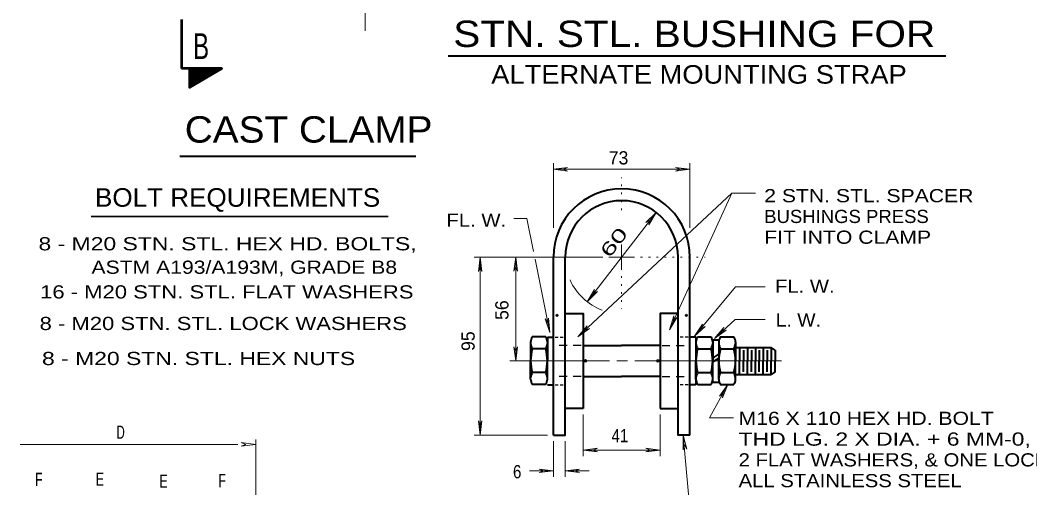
# Model space of a CAD drawing. Extents: x 312583 to 312854, y 144419 to 144597.
# Drawn here: x 312665.2 to 312723.4, y 144516.8 to 144543.7 of the extents above; entities that cross this region are included whole.
import ezdxf
from ezdxf.enums import TextEntityAlignment as Align

# ---------------------------------------------------------------- set-up
doc = ezdxf.new("R2010")
doc.units = 0
doc.header["$LTSCALE"] = 0.3
doc.header["$PDMODE"] = 32
doc.header["$PDSIZE"] = 0.15
doc.linetypes.add('DOTTED', pattern=[1.5, 0.3, -1.2])
doc.linetypes.add('SHORT_DASHED', pattern=[2.7, 1.5, -1.2])
doc.layers.add('1', color=7, linetype='Continuous', lineweight=13)

msp = doc.modelspace()

# ---------------------------------------------------------------- linework, layer by layer
at = {"layer": '1'}
for p, q in [((312685.0876, 144545.2113), (312685.0876, 144543.1183)), ((312695.9432, 144531.7582), (312695.9432, 144535.4842)), ((312703.8169, 144531.7582), (312703.8169, 144535.4842)), ((312695.9432, 144535.1392), (312696.7635, 144535.2389)), ((312695.9432, 144535.1392), (312703.8169, 144535.1392)), ((312695.9432, 144535.1392), (312696.7635, 144535.0396)), ((312696.7635, 144535.2389), (312696.5029, 144535.1392)), ((312696.7635, 144535.0396), (312696.5029, 144535.1392)), ((312702.9889, 144535.2389), (312703.2495, 144535.1392)), ((312703.8169, 144535.1392), (312702.9889, 144535.2389)), ((312702.9889, 144535.0396), (312703.2495, 144535.1392)), ((312703.8169, 144535.1392), (312702.9889, 144535.0396)), ((312697.3539, 144525.4716), (312706.2319, 144533.7592)), ((312702.6285, 144525.8932), (312706.2319, 144533.7592)), ((312706.2319, 144533.7592), (312707.5965, 144533.7592)), ((312697.8982, 144527.4956), (312701.8619, 144532.6552)), ((312701.8619, 144532.6552), (312701.2792, 144532.0649)), ((312701.8619, 144532.6552), (312701.4402, 144531.9422)), ((312693.6586, 144532.3102), (312694.4099, 144532.3102)), ((312694.4099, 144532.3102), (312694.7932, 144530.4012)), ((312701.2792, 144532.0649), (312701.5169, 144532.2106)), ((312701.4402, 144531.9422), (312701.5169, 144532.2106)), ((312699.8762, 144530.0792), (312699.8762, 144530.8076)), ((312698.7875, 144530.0792), (312691.3739, 144530.0792)), ((312691.7189, 144530.0792), (312691.6192, 144529.2512)), ((312691.6192, 144529.2512), (312691.7189, 144529.5119)), ((312691.7189, 144530.0792), (312691.7189, 144519.8059)), ((312691.7189, 144530.0792), (312691.8185, 144529.2512)), ((312691.8185, 144529.2512), (312691.7189, 144529.5119)), ((312693.7735, 144530.0792), (312693.6662, 144529.2589)), ((312693.6662, 144529.2589), (312693.7735, 144529.5196)), ((312693.7735, 144524.0916), (312693.7735, 144530.0792)), ((312693.7735, 144530.0792), (312693.8732, 144529.2589)), ((312693.8732, 144529.2589), (312693.7735, 144529.5196)), ((312694.8852, 144529.9489), (312695.7285, 144525.7322)), ((312699.8762, 144530.0792), (312699.1479, 144530.0792)), ((312699.8762, 144530.0792), (312699.8762, 144529.3432)), ((312699.8762, 144530.0792), (312700.6122, 144530.0792)), ((312706.4465, 144528.3619), (312704.0852, 144525.5099)), ((312706.4465, 144528.3619), (312708.1562, 144528.3619)), ((312697.8982, 144527.4956), (312698.3199, 144528.2162)), ((312697.8982, 144527.4956), (312698.4809, 144528.0859)), ((312698.3199, 144528.2162), (312698.2432, 144527.9402)), ((312698.4809, 144528.0859), (312698.2432, 144527.9402)), ((312702.6285, 144525.8932), (312702.8815, 144526.6829)), ((312702.8815, 144526.6829), (312702.8585, 144526.4069)), ((312695.4679, 144526.5219), (312695.6212, 144526.2842)), ((312695.7285, 144525.7322), (312695.4679, 144526.5219)), ((312695.6672, 144526.5602), (312695.6212, 144526.2842)), ((312695.7285, 144525.7322), (312695.6672, 144526.5602)), ((312697.3539, 144525.4716), (312697.8829, 144526.1079)), ((312697.8829, 144526.1079), (312697.7602, 144525.8549)), ((312702.6285, 144525.8932), (312703.0579, 144526.5986)), ((312703.0579, 144526.5986), (312702.8585, 144526.4069)), ((312704.0852, 144525.5099), (312704.5375, 144526.2076)), ((312704.0852, 144525.5099), (312704.6909, 144526.0772)), ((312704.5375, 144526.2076), (312704.4455, 144525.9392)), ((312704.6909, 144526.0772), (312704.4455, 144525.9392)), ((312706.4159, 144526.4836), (312705.2275, 144525.3796)), ((312706.4159, 144526.4836), (312708.1485, 144526.4836)), ((312697.3539, 144525.4716), (312698.0285, 144525.9622)), ((312698.0285, 144525.9622), (312697.7602, 144525.8549)), ((312705.2275, 144525.3796), (312705.7642, 144526.0159)), ((312705.2275, 144525.3796), (312705.9022, 144525.8626)), ((312705.7642, 144526.0159), (312705.6415, 144525.7629)), ((312705.9022, 144525.8626), (312705.6415, 144525.7629)), ((312693.6662, 144524.9119), (312693.7735, 144524.6512)), ((312693.7735, 144524.0916), (312693.6662, 144524.9119)), ((312693.8732, 144524.9119), (312693.7735, 144524.6512)), ((312693.7735, 144524.0916), (312693.8732, 144524.9119)), ((312699.1862, 144524.0916), (312693.4285, 144524.0916)), ((312700.2212, 144524.0916), (312699.5925, 144524.0916)), ((312700.6352, 144524.0916), (312709.0992, 144524.0916)), ((312706.0019, 144522.7269), (312704.9515, 144520.8026)), ((312706.0019, 144522.7269), (312705.5189, 144522.0522)), ((312706.0019, 144522.7269), (312705.7029, 144521.9602)), ((312705.5189, 144522.0522), (312705.7335, 144522.2362)), ((312705.7029, 144521.9602), (312705.7335, 144522.2362)), ((312697.6529, 144518.6099), (312697.6529, 144521.0096)), ((312702.1072, 144518.6099), (312702.1072, 144521.0096)), ((312706.3239, 144520.8026), (312704.9515, 144520.8026)), ((312691.6192, 144520.6339), (312691.7189, 144520.3732)), ((312691.7189, 144519.8059), (312691.6192, 144520.6339)), ((312691.8185, 144520.6339), (312691.7189, 144520.3732)), ((312691.7189, 144519.8059), (312691.8185, 144520.6339)), ((312695.5982, 144519.8059), (312691.3739, 144519.8059)), ((312703.4335, 144519.8059), (312703.4265, 144518.9762)), ((312703.4335, 144519.8059), (312703.6281, 144518.9962)), ((312665.1937, 144519.2818), (312677.7363, 144519.2818)), ((312677.9433, 144519.3891), (312678.2117, 144519.2818)), ((312678.7867, 144519.2818), (312677.9433, 144519.3891)), ((312677.9433, 144519.1821), (312678.2117, 144519.2818)), ((312678.7867, 144519.2818), (312677.9433, 144519.1821)), ((312678.7867, 144513.9841), (312678.7867, 144519.5578)), ((312695.9432, 144519.4686), (312695.9432, 144517.4062)), ((312696.6255, 144519.4686), (312696.6255, 144517.4062)), ((312697.6529, 144518.9549), (312698.4809, 144519.0546)), ((312698.4809, 144519.0546), (312698.2125, 144518.9549)), ((312701.2792, 144519.0546), (312701.5475, 144518.9549)), ((312702.1072, 144518.9549), (312701.2792, 144519.0546)), ((312703.4265, 144518.9762), (312703.4963, 144519.2502)), ((312703.6281, 144518.9962), (312703.4963, 144519.2502)), ((312697.6529, 144518.9549), (312702.1072, 144518.9549)), ((312697.6529, 144518.9549), (312698.4809, 144518.8552)), ((312698.4809, 144518.8552), (312698.2125, 144518.9549)), ((312701.2792, 144518.8552), (312701.5475, 144518.9549)), ((312702.1072, 144518.9549), (312701.2792, 144518.8552)), ((312695.9432, 144517.7512), (312694.5709, 144517.7512)), ((312695.1152, 144517.8509), (312695.3835, 144517.7512)), ((312695.9432, 144517.7512), (312695.1152, 144517.8509)), ((312695.1152, 144517.6516), (312695.3835, 144517.7512)), ((312695.9432, 144517.7512), (312695.1152, 144517.6516)), ((312696.6255, 144517.7512), (312697.4535, 144517.8509)), ((312697.9979, 144517.7512), (312696.6255, 144517.7512)), ((312696.6255, 144517.7512), (312697.4535, 144517.6516)), ((312697.4535, 144517.8509), (312697.1852, 144517.7512)), ((312697.4535, 144517.6516), (312697.1852, 144517.7512))]:
    msp.add_line(p, q, dxfattribs=at)
at = {"layer": '1', "lineweight": 53}
for p in [(312674.4922, 144543.7776), (312674.9522, 144540.9409)]:
    msp.add_line(p, (312674.4922, 144540.9409), dxfattribs=at)
at = {"layer": '1', "lineweight": 40}
for p, q in [((312689.8769, 144541.6789), (312718.5793, 144541.6789)), ((312674.4041, 144535.8982), (312688.0124, 144535.8982)), ((312695.9432, 144519.8059), (312695.9432, 144530.0792)), ((312703.8169, 144519.8059), (312703.8169, 144530.0792)), ((312695.5062, 144525.4716), (312694.7242, 144525.4716)), ((312695.5982, 144525.4562), (312695.9432, 144525.4562)), ((312695.5982, 144525.4562), (312695.5982, 144524.0916)), ((312704.1619, 144525.4562), (312703.8169, 144525.4562)), ((312704.1619, 144525.4562), (312704.1619, 144522.7192)), ((312704.2462, 144525.4716), (312705.0359, 144525.4716)), ((312705.5649, 144525.4716), (312706.3469, 144525.4716)), ((312694.6245, 144525.1726), (312694.6245, 144524.0839)), ((312695.5982, 144525.1726), (312695.5982, 144524.0916)), ((312697.6529, 144524.9886), (312699.8762, 144524.9886)), ((312702.1072, 144524.9886), (312699.8762, 144524.9886)), ((312704.1619, 144525.1726), (312704.1619, 144524.0916)), ((312705.1279, 144525.3106), (312705.4729, 144525.3106)), ((312705.1279, 144525.3106), (312705.1279, 144525.1726)), ((312705.1279, 144525.1726), (312705.1279, 144524.0839)), ((312705.4729, 144525.3106), (312705.4729, 144525.1726)), ((312705.4729, 144525.1726), (312705.4729, 144524.0839)), ((312706.4465, 144525.1649), (312706.4465, 144524.0839)), ((312706.6765, 144524.8736), (312706.6765, 144524.0839)), ((312707.1289, 144524.8736), (312707.1289, 144524.0839)), ((312707.5889, 144524.8736), (312707.5889, 144524.0839)), ((312708.0412, 144524.8736), (312708.0412, 144524.0839)), ((312708.7312, 144524.7126), (312708.5012, 144524.8736)), ((312695.5062, 144524.7892), (312694.7242, 144524.7892)), ((312704.2539, 144524.7892), (312705.0359, 144524.7892)), ((312705.1279, 144524.2602), (312705.4729, 144524.4826)), ((312705.5649, 144524.7816), (312706.3469, 144524.7816)), ((312706.9065, 144524.7126), (312706.9065, 144524.0839)), ((312707.3589, 144524.7126), (312707.3589, 144524.0839)), ((312707.8112, 144524.7126), (312707.8112, 144524.0839)), ((312708.2712, 144524.7126), (312708.2712, 144524.0839)), ((312708.7312, 144524.7126), (312708.7312, 144524.0839)), ((312694.6245, 144523.0336), (312694.6245, 144524.0916)), ((312695.5982, 144523.0336), (312695.5982, 144524.0916)), ((312704.1619, 144523.0336), (312704.1619, 144524.0916)), ((312705.1279, 144524.0302), (312705.4729, 144524.2526)), ((312705.1279, 144523.0336), (312705.1279, 144524.0916)), ((312705.4729, 144523.0259), (312705.4729, 144524.0839)), ((312706.4465, 144523.0336), (312706.4465, 144524.0916)), ((312706.6765, 144523.3019), (312706.6765, 144524.0916)), ((312706.9065, 144523.4629), (312706.9065, 144524.0916)), ((312707.1289, 144523.3019), (312707.1289, 144524.0916)), ((312707.3589, 144523.4629), (312707.3589, 144524.0916)), ((312707.5889, 144523.3019), (312707.5889, 144524.0916)), ((312707.8112, 144523.4629), (312707.8112, 144524.0916)), ((312708.0412, 144523.3019), (312708.0412, 144524.0916)), ((312708.2712, 144523.4629), (312708.2712, 144524.0916)), ((312708.5012, 144523.3019), (312708.5012, 144524.0916)), ((312708.7312, 144523.4629), (312708.7312, 144524.0916)), ((312695.5062, 144523.4246), (312694.7242, 144523.4246)), ((312697.6529, 144523.1869), (312699.8762, 144523.1869)), ((312702.1072, 144523.1869), (312699.8762, 144523.1869)), ((312704.2462, 144523.4246), (312705.0359, 144523.4246)), ((312705.5649, 144523.4246), (312706.3469, 144523.4246)), ((312706.4465, 144523.3019), (312708.5012, 144523.3019)), ((312708.7312, 144523.4629), (312708.5012, 144523.3019)), ((312695.5062, 144522.7346), (312694.7242, 144522.7346)), ((312695.5982, 144522.7192), (312695.9432, 144522.7192)), ((312704.1619, 144522.7192), (312703.8169, 144522.7192)), ((312704.2462, 144522.7346), (312705.0359, 144522.7346)), ((312705.1279, 144522.8726), (312705.1279, 144523.0336)), ((312705.1279, 144522.8726), (312705.4729, 144522.8726)), ((312705.4729, 144523.0259), (312705.4729, 144522.8726)), ((312705.5649, 144522.7269), (312706.3469, 144522.7269)), ((312697.6529, 144521.3469), (312696.6255, 144521.3469)), ((312702.1072, 144521.3469), (312703.1345, 144521.3469))]:
    msp.add_line(p, q, dxfattribs=at)
at = {"layer": '1', "lineweight": 35}
for p, q in [((312674.9522, 144540.9179), (312675.4122, 144540.1283)), ((312674.9522, 144540.8643), (312675.3816, 144540.1206)), ((312674.9522, 144540.8259), (312675.3739, 144540.1053)), ((312674.9522, 144540.7723), (312675.3509, 144540.0976)), ((312674.9522, 144540.7263), (312675.3279, 144540.0823)), ((312674.9522, 144540.6803), (312675.3126, 144540.0669)), ((312674.9522, 144540.6419), (312675.2896, 144540.0593)), ((312674.9522, 144540.5883), (312675.2666, 144540.0439)), ((312674.9676, 144540.9409), (312675.4276, 144540.1436)), ((312674.9982, 144540.9409), (312675.4506, 144540.1513)), ((312675.0289, 144540.9409), (312675.4736, 144540.1666)), ((312675.0519, 144540.9409), (312675.4889, 144540.1743)), ((312675.0826, 144540.9409), (312675.5119, 144540.1896)), ((312675.1056, 144540.9256), (312675.5349, 144540.1896)), ((312675.1286, 144540.9256), (312675.5502, 144540.2126)), ((312675.1516, 144540.9409), (312675.5732, 144540.2126)), ((312675.1822, 144540.9409), (312675.5962, 144540.2356)), ((312675.2129, 144540.9409), (312675.6116, 144540.2433)), ((312675.2359, 144540.9409), (312675.6269, 144540.2509)), ((312675.2666, 144540.9409), (312675.6499, 144540.2663)), ((312675.2972, 144540.9409), (312675.6729, 144540.2816)), ((312675.3202, 144540.9409), (312675.6882, 144540.2893)), ((312675.3509, 144540.9256), (312675.7112, 144540.3046)), ((312675.3739, 144540.9409), (312675.7342, 144540.3123)), ((312675.3969, 144540.9409), (312675.7496, 144540.3276)), ((312675.4199, 144540.9409), (312675.7726, 144540.3353)), ((312675.4506, 144540.9409), (312675.7956, 144540.3506)), ((312675.4812, 144540.9409), (312675.8109, 144540.3583)), ((312675.5119, 144540.9409), (312675.8339, 144540.3736)), ((312675.5349, 144540.9409), (312675.8569, 144540.3813)), ((312675.5656, 144540.9409), (312675.8646, 144540.3966)), ((312675.5886, 144540.9256), (312675.8952, 144540.4043)), ((312675.6192, 144540.9409), (312675.9106, 144540.4196)), ((312675.6422, 144540.9409), (312675.9336, 144540.4349)), ((312675.6652, 144540.9409), (312675.9566, 144540.4349)), ((312675.6959, 144540.9409), (312675.9719, 144540.4579)), ((312675.7189, 144540.9409), (312675.9949, 144540.4579)), ((312675.7496, 144540.9409), (312676.0179, 144540.4809)), ((312675.7802, 144540.9409), (312676.0332, 144540.4809)), ((312675.8032, 144540.9409), (312676.0562, 144540.4963)), ((312675.8339, 144540.9409), (312676.0792, 144540.5039)), ((312675.8646, 144540.9409), (312676.0869, 144540.5193)), ((312675.8876, 144540.9409), (312676.1099, 144540.5269)), ((312675.9029, 144540.9409), (312676.1329, 144540.5423)), ((312675.9336, 144540.9409), (312676.1559, 144540.5499)), ((312675.9642, 144540.9409), (312676.1712, 144540.5653)), ((312675.9949, 144540.9409), (312676.1942, 144540.5806)), ((312676.0179, 144540.9409), (312676.2172, 144540.5883)), ((312676.0486, 144540.9409), (312676.2326, 144540.6036)), ((312676.0716, 144540.9409), (312676.2556, 144540.6189)), ((312676.1022, 144540.9409), (312676.2786, 144540.6266)), ((312676.1176, 144540.9409), (312676.2939, 144540.6419)), ((312676.1482, 144540.9409), (312676.3169, 144540.6496)), ((312676.1789, 144540.9409), (312676.3322, 144540.6649)), ((312676.2019, 144540.9409), (312676.3552, 144540.6726)), ((312676.2326, 144540.9409), (312676.3782, 144540.6803)), ((312676.2556, 144540.9409), (312676.3936, 144540.6956)), ((312676.2862, 144540.9409), (312676.4166, 144540.7033)), ((312676.3169, 144540.9409), (312676.4396, 144540.7109)), ((312676.3322, 144540.9409), (312676.4549, 144540.7263)), ((312676.3629, 144540.9409), (312676.4779, 144540.7339)), ((312676.3859, 144540.9409), (312676.5009, 144540.7493)), ((312676.4166, 144540.9409), (312676.5162, 144540.7646)), ((312676.4472, 144540.9409), (312676.5392, 144540.7723)), ((312676.4779, 144540.9409), (312676.5622, 144540.7876)), ((312676.5009, 144540.9409), (312676.5776, 144540.8029)), ((312676.5316, 144540.9409), (312676.6006, 144540.8106)), ((312676.5546, 144540.9409), (312676.6236, 144540.8259)), ((312676.5776, 144540.9409), (312676.6389, 144540.8336)), ((312676.6006, 144540.9409), (312676.6542, 144540.8489)), ((312676.6312, 144540.9409), (312676.6772, 144540.8566)), ((312676.6619, 144540.9409), (312676.7002, 144540.8719)), ((312676.6849, 144540.9409), (312676.7156, 144540.8796)), ((312676.7156, 144540.9409), (312676.7386, 144540.8949)), ((312676.7386, 144540.9409), (312676.7616, 144540.9026)), ((312676.7692, 144540.9409), (312676.7769, 144540.9179)), ((312676.7999, 144540.9409), (312676.7999, 144540.9256)), ((312674.9522, 144540.5423), (312675.2512, 144540.0286)), ((312674.9522, 144540.4963), (312675.2282, 144540.0209)), ((312674.9522, 144540.4503), (312675.2129, 144540.0056)), ((312674.9522, 144540.4043), (312675.1899, 144539.9979)), ((312674.9522, 144540.3583), (312675.1669, 144539.9903)), ((312674.9522, 144540.3046), (312675.1516, 144539.9749)), ((312674.9522, 144540.2586), (312675.1286, 144539.9673)), ((312674.9522, 144540.2126), (312675.1056, 144539.9596)), ((312674.9522, 144540.1743), (312675.0902, 144539.9443)), ((312674.9522, 144540.1206), (312675.0672, 144539.9366)), ((312674.9522, 144540.0823), (312675.0519, 144539.9213)), ((312674.9522, 144540.0286), (312675.0289, 144539.9136)), ((312674.9522, 144539.9903), (312675.0059, 144539.8983)), ((312674.9522, 144539.9366), (312674.9906, 144539.8829)), ((312674.9522, 144539.8906), (312674.9676, 144539.8753)), ((312669.2792, 144532.4252), (312686.4218, 144532.4252))]:
    msp.add_line(p, q, dxfattribs=at)
at = {"layer": '1', "linetype": 'DOTTED'}
for p, q in [((312699.8762, 144532.7779), (312699.8762, 144534.6639)), ((312700.9725, 144530.0792), (312704.6909, 144530.0792)), ((312699.8762, 144528.9829), (312699.8762, 144527.1046))]:
    msp.add_line(p, q, dxfattribs=at)
at = {"layer": '1', "lineweight": 25}
for p, q in [((312696.0429, 144525.4562), (312696.2192, 144525.4562)), ((312696.3265, 144525.4562), (312696.5105, 144525.4562)), ((312703.4335, 144525.4562), (312703.2495, 144525.4562)), ((312703.7172, 144525.4562), (312703.5409, 144525.4562)), ((312696.0429, 144522.7192), (312696.2192, 144522.7192)), ((312696.3265, 144522.7192), (312696.5105, 144522.7192)), ((312703.4335, 144522.7192), (312703.2495, 144522.7192)), ((312703.7172, 144522.7192), (312703.5409, 144522.7192))]:
    msp.add_line(p, q, dxfattribs=at)
at = {"layer": '1', "linetype": 'SHORT_DASHED', "lineweight": 25}
for p, q in [((312697.5379, 144524.9886), (312696.0659, 144524.9886)), ((312702.2145, 144524.9886), (312703.6942, 144524.9886)), ((312697.5379, 144523.1869), (312696.0659, 144523.1869)), ((312702.2145, 144523.1869), (312703.6942, 144523.1869))]:
    msp.add_line(p, q, dxfattribs=at)
at = {"layer": '1', "lineweight": 53}
msp.add_lwpolyline([(312674.9522, 144540.9409), (312674.9522, 144539.8599), (312676.8152, 144540.9409)], close=True, dxfattribs=at)
at = {"layer": '1', "lineweight": 40}
for points in [[(312695.9432, 144519.8059), (312696.6255, 144519.8059), (312696.6255, 144530.0792)], [(312703.8169, 144519.8059), (312703.1345, 144519.8059), (312703.1345, 144530.0792)], [(312696.6255, 144526.8286), (312697.6529, 144526.8286), (312697.6529, 144521.3469)], [(312703.1345, 144526.8286), (312702.1072, 144526.8286), (312702.1072, 144521.3469)], [(312706.4465, 144524.8736), (312708.5012, 144524.8736), (312708.5012, 144524.0839)]]:
    msp.add_lwpolyline(points, dxfattribs=at)
at = {"layer": '1'}
msp.add_lwpolyline([(312703.4335, 144519.8059), (312703.8195, 144515.3367), (312702.4549, 144515.3367)], dxfattribs=at)
at = {"layer": '1', "lineweight": 40}
for centre, radius, start, end in [((312699.8795, 144530.0765), 3.9374, 90, 180), ((312699.8795, 144530.0765), 3.9374, 0, 90), ((312699.8795, 144530.0765), 3.2529, 90, 180), ((312699.8795, 144530.0765), 3.2529, 0, 90), ((312695.1905, 144525.1543), 0.5638, 145.8703, 178.33743), ((312695.0352, 144525.1543), 0.5638, 1.66257, 34.1297), ((312704.7238, 144525.1543), 0.5638, 145.8703, 178.33743), ((312704.5685, 144525.1543), 0.5638, 1.66257, 34.1297), ((312706.0381, 144525.1516), 0.5638, 145.8703, 178.33743), ((312705.8827, 144525.1516), 0.5638, 1.66257, 34.1297), ((312696.2058, 144525.4265), 1.6143, 191.77014, 203.36365), ((312694.0199, 144525.4265), 1.6143, 336.63635, 348.22986), ((312705.7391, 144525.4265), 1.6143, 191.77014, 203.36365), ((312703.5531, 144525.4265), 1.6143, 336.63635, 348.22986), ((312707.0534, 144525.4238), 1.6143, 191.77014, 203.36365), ((312704.8674, 144525.4238), 1.6143, 336.63635, 348.22986), ((312697.538, 144524.0322), 2.9134, 164.99798, 178.595), ((312692.6877, 144524.0322), 2.9134, 1.405, 15.00202), ((312707.0712, 144524.0322), 2.9134, 164.99798, 178.595), ((312702.221, 144524.0322), 2.9134, 1.405, 15.00202), ((312708.3855, 144524.0294), 2.9134, 164.99798, 178.595), ((312703.5353, 144524.0294), 2.9134, 1.405, 15.00202), ((312697.538, 144524.1751), 2.9134, 181.405, 195.00202), ((312692.6877, 144524.1751), 2.9134, 344.99798, 358.595), ((312707.0712, 144524.1751), 2.9134, 181.405, 195.00202), ((312702.221, 144524.1751), 2.9134, 344.99798, 358.595), ((312708.3855, 144524.1723), 2.9134, 181.405, 195.00202), ((312703.5353, 144524.1723), 2.9134, 344.99798, 358.595), ((312696.2058, 144522.7807), 1.6143, 156.63635, 168.22986), ((312694.0199, 144522.7807), 1.6143, 11.77014, 23.36365), ((312705.7391, 144522.7807), 1.6143, 156.63635, 168.22986), ((312703.5531, 144522.7807), 1.6143, 11.77014, 23.36365), ((312707.0534, 144522.778), 1.6143, 156.63635, 168.22986), ((312704.8674, 144522.778), 1.6143, 11.77014, 23.36365), ((312695.1905, 144523.053), 0.5638, 181.66257, 214.1297), ((312695.0352, 144523.053), 0.5638, 325.8703, 358.33743), ((312704.7238, 144523.053), 0.5638, 181.66257, 214.1297), ((312704.5685, 144523.053), 0.5638, 325.8703, 358.33743), ((312706.0381, 144523.0502), 0.5638, 181.66257, 214.1297), ((312705.8827, 144523.0502), 0.5638, 325.8703, 358.33743)]:
    msp.add_arc(centre, radius, start, end, dxfattribs=at)
at = {"layer": '1'}
msp.add_arc((312699.8795, 144530.0765), 3.2529, 203.82541, 249.8142, dxfattribs=at)
for p in [(312696.1502, 144526.7212), (312703.6099, 144526.7212), (312697.7985, 144524.0916), (312701.9615, 144524.0916)]:
    msp.add_point(p, dxfattribs=at)

# ---------------------------------------------------------------- texts
for s, height, width, p in [('STN. STL. BUSHING FOR', 1.52, 1.15, (312690.1677, 144542.1907)), ('CAST CLAMP', 1.52, 1.1, (312674.6828, 144536.6766)), ('2 STN. STL. SPACER', 0.76, 1.2, (312708.1005, 144533.2388)), ('FL. W.', 0.76, 1.15, (312689.7754, 144531.826)), ('BUSHINGS PRESS', 0.76, 1.05, (312708.1005, 144532.0418)), ('FIT INTO CLAMP', 0.76, 1.2, (312708.1005, 144530.8448)), (' 8 - M20 STN. STL. HEX HD. BOLTS,', 0.76, 1.3, (312665.8822, 144530.4662)), ('ASTM A193/A193M, GRADE B8', 0.76, 1.2, (312669.3048, 144529.1139)), ('16 - M20 STN. STL. FLAT WASHERS', 0.76, 1.25, (312666.3422, 144527.6909)), ('FL. W.', 0.76, 1.15, (312708.7191, 144528.0185)), (' 8 - M20 STN. STL. LOCK WASHERS', 0.76, 1.25, (312665.9607, 144525.8709)), ('L. W.', 0.76, 1.1, (312708.7624, 144526.0731)), (' 8 - M20 STN. STL. HEX NUTS', 0.76, 1.3, (312666.0842, 144523.8528)), ('M16 X 110 HEX HD. BOLT', 0.76, 1.2, (312706.6229, 144520.4029)), ('D', 0.76, 0.65, (312670.7482, 144519.6048)), ('41', 0.76, 0.85, (312699.2981, 144519.4064)), ('THD LG. 2 X DIA. + 6 MM-0, 2 HEX NUTS,', 0.76, 1.3, (312706.6229, 144519.2059)), ('2 FLAT WASHERS, & ONE LOCK WASHER', 0.76, 1.15, (312706.6229, 144518.0089)), ('6', 0.76, 0.85, (312693.6121, 144517.3273)), ('F', 0.76, 0.7, (312666.0503, 144516.8851)), ('E', 0.76, 0.7, (312669.5531, 144516.8955)), ('E', 0.76, 0.7, (312673.2246, 144516.7814)), ('F', 0.76, 0.7, (312676.6223, 144516.8142)), ('ALL STAINLESS STEEL', 0.76, 1.15, (312706.6229, 144516.8119))]:
    msp.add_text(s, height=height, dxfattribs=dict(at, width=width)).set_placement(p)
for s, height, width, p in [('B', 1.489, 0.7, (312675.623, 144541.4929)), ('ALTERNATE MOUNTING STRAP', 1.07, 1.1, (312704.3387, 144540.0747)), ('BOLT REQUIREMENTS', 1.07, 1.05, (312677.7296, 144532.979))]:
    msp.add_text(s, height=height, dxfattribs=dict(at, width=width)).set_placement(p, align=Align.CENTER)
msp.add_text('73', height=0.76, dxfattribs=at).set_placement((312699.1345, 144535.4209))
at = {"layer": '1', "width": 1.6}
msp.add_text('60', height=0.76, rotation=52.455, dxfattribs=at).set_placement((312699.1804, 144529.9838))
at = {"layer": '1'}
for s, p in [('56', (312693.3505, 144526.4553)), ('95', (312691.4022, 144524.666))]:
    msp.add_text(s, height=0.76, rotation=90, dxfattribs=at).set_placement(p)

doc.saveas('drawing.dxf')
